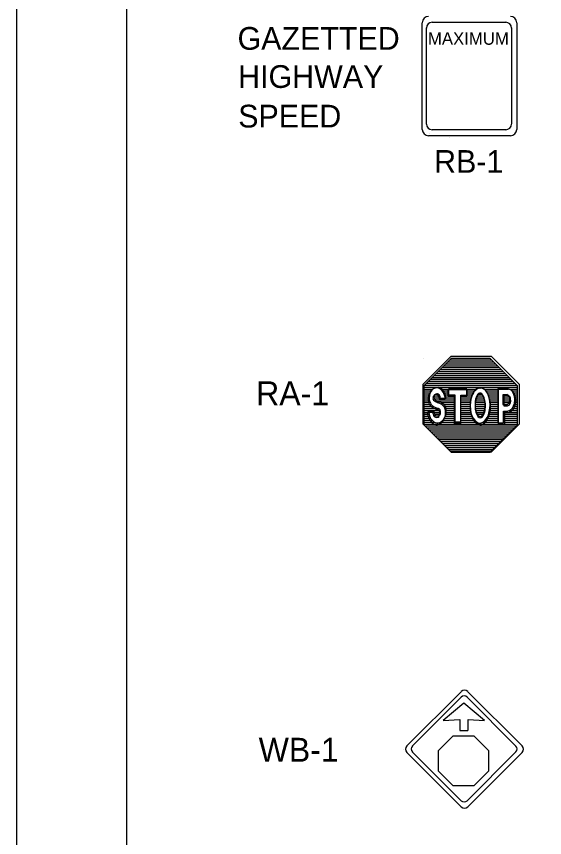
# Model space of a CAD drawing. Extents: x 1314 to 1530, y 165 to 444.
# Drawn here: x 1313.8 to 1361.9, y 296.1 to 370.9 of the extents above; entities that cross this region are included whole.
import ezdxf

# ---------------------------------------------------------------- set-up
doc = ezdxf.new("R2010")
doc.units = 0
for name, color, linetype in [('Level 10', 7, 'Continuous'), ('Level 44', 7, 'Continuous'), ('Level 60', 7, 'Continuous')]:
    doc.layers.add(name, color=color, linetype=linetype)

msp = doc.modelspace()

# ---------------------------------------------------------------- linework, layer by layer
at = {"layer": 'Level 10'}
msp.add_lwpolyline([(1353.534, 305.411), (1355.421, 305.411), (1356.754, 304.079), (1356.754, 302.198), (1355.421, 300.865), (1353.534, 300.865), (1352.208, 302.198), (1352.208, 304.079)], close=True, dxfattribs=at)
at = {"layer": 'Level 44'}
for p, q in [((1350.724, 360.601), (1350.724, 370.311)), ((1351.624, 370.349), (1358.328, 370.349)), ((1359.322, 370.311), (1359.322, 360.601)), ((1351.107, 361.094), (1351.107, 369.832)), ((1358.846, 369.832), (1358.846, 361.094)), ((1351.107, 361.091), (1351.107, 361.094)), ((1350.724, 360.598), (1350.724, 360.601)), ((1351.43, 360.265), (1351.43, 360.265)), ((1358.328, 360.575), (1351.624, 360.575)), ((1358.746, 360.025), (1351.298, 360.025)), ((1353.178, 359.867), (1353.178, 359.867)), ((1353.375, 339.742), (1350.888, 337.256)), ((1350.888, 339.742), (1350.888, 339.742)), ((1356.916, 339.742), (1353.375, 339.742)), ((1359.403, 337.256), (1356.916, 339.742)), ((1350.888, 337.256), (1350.888, 333.714)), ((1359.403, 333.714), (1359.403, 337.256)), ((1353.083, 336.359), (1353.083, 336.918)), ((1353.083, 336.918), (1354.782, 336.918)), ((1353.671, 336.359), (1353.083, 336.359)), ((1353.134, 336.986), (1353.134, 336.441)), ((1354.791, 336.986), (1353.134, 336.986)), ((1353.134, 336.441), (1353.708, 336.441)), ((1353.671, 333.848), (1353.671, 336.359)), ((1353.708, 336.441), (1353.708, 333.99)), ((1354.782, 336.345), (1354.223, 336.345)), ((1354.223, 336.345), (1354.223, 333.848)), ((1354.246, 333.99), (1354.246, 336.427)), ((1354.246, 336.427), (1354.791, 336.427)), ((1354.782, 336.918), (1354.782, 336.345)), ((1354.791, 336.427), (1354.791, 336.986)), ((1355.958, 336.516), (1355.981, 336.52)), ((1355.98, 337.059), (1355.996, 337.06)), ((1358.489, 337.015), (1357.618, 337.015)), ((1357.618, 337.015), (1357.618, 333.898)), ((1357.677, 333.754), (1357.677, 336.947)), ((1357.677, 336.947), (1358.571, 336.947)), ((1358.411, 336.456), (1358.07, 336.456)), ((1358.07, 336.456), (1358.07, 335.549)), ((1358.07, 336.456), (1358.07, 335.549)), ((1358.411, 336.456), (1358.07, 336.456)), ((1358.143, 336.374), (1358.143, 335.445)), ((1358.49, 336.374), (1358.143, 336.374)), ((1358.49, 336.374), (1358.143, 336.374)), ((1358.143, 336.374), (1358.143, 335.445)), ((1352.822, 336.025), (1352.277, 336.025)), ((1352.879, 336.116), (1352.347, 336.116)), ((1351.204, 334.879), (1351.704, 334.879)), ((1351.299, 334.996), (1351.788, 334.996)), ((1358.07, 335.549), (1358.404, 335.549)), ((1358.07, 335.549), (1358.404, 335.549)), ((1358.134, 333.898), (1358.134, 334.961)), ((1358.134, 334.961), (1358.461, 334.961)), ((1358.143, 335.445), (1358.483, 335.445)), ((1358.143, 335.445), (1358.483, 335.445)), ((1358.525, 334.85), (1358.207, 334.842)), ((1358.207, 334.842), (1358.541, 334.842)), ((1358.207, 334.842), (1358.207, 333.754)), ((1351.363, 334.247), (1351.36, 334.249)), ((1350.888, 333.714), (1353.375, 331.228)), ((1354.223, 333.848), (1353.671, 333.848)), ((1353.708, 333.99), (1354.246, 333.99)), ((1356.916, 331.228), (1359.403, 333.714)), ((1357.618, 333.898), (1358.134, 333.898)), ((1358.207, 333.754), (1357.677, 333.754)), ((1353.375, 331.228), (1356.916, 331.228)), ((1354.283, 309.427), (1349.335, 304.486)), ((1359.809, 304.486), (1354.868, 309.427)), ((1349.829, 304.482), (1354.283, 308.929)), ((1354.808, 308.929), (1359.256, 304.482)), ((1354.518, 308.391), (1352.648, 306.814)), ((1356.388, 306.814), (1354.518, 308.391)), ((1352.648, 306.814), (1354.143, 306.895)), ((1354.143, 306.895), (1354.143, 305.896)), ((1354.893, 305.896), (1354.893, 306.895)), ((1354.893, 306.895), (1356.388, 306.814)), ((1354.143, 305.896), (1354.888, 305.896)), ((1349.04, 304.196), (1349.04, 304.196)), ((1349.335, 303.899), (1354.283, 298.952)), ((1349.338, 303.899), (1349.335, 303.899)), ((1354.283, 299.503), (1349.829, 303.953)), ((1359.256, 303.953), (1354.808, 299.503)), ((1354.868, 298.952), (1359.809, 303.899))]:
    msp.add_line(p, q, dxfattribs=at)
msp.add_lwpolyline([(1359.552, 333.776), (1357.004, 331.228), (1353.375, 331.228), (1350.827, 333.776), (1350.827, 337.405), (1353.375, 339.953), (1357.004, 339.953), (1359.552, 337.405)], close=True, dxfattribs=at)
for points in [[(1353.084, 339.452), (1357.2, 339.452)], [(1353.261, 339.628), (1357.029, 339.628)], [(1352.199, 338.566), (1358.092, 338.566)], [(1352.376, 338.743), (1357.915, 338.743)], [(1352.553, 338.92), (1357.73, 338.92)], [(1352.73, 339.097), (1357.561, 339.097)], [(1352.907, 339.274), (1357.383, 339.274)], [(1351.49, 337.858), (1358.8, 337.858)], [(1351.667, 338.035), (1358.623, 338.035)], [(1351.844, 338.212), (1358.446, 338.212)], [(1352.022, 338.389), (1358.269, 338.389)], [(1350.888, 337.149), (1359.403, 337.149)], [(1350.959, 337.327), (1359.332, 337.327)], [(1351.136, 337.503), (1359.154, 337.503)], [(1351.314, 337.681), (1358.978, 337.681)], [(1350.888, 336.972), (1351.71, 336.972)], [(1350.888, 336.795), (1351.561, 336.795)], [(1350.888, 336.618), (1351.462, 336.618)], [(1350.888, 336.441), (1351.412, 336.441)], [(1351.88, 336.441), (1352.276, 336.441)], [(1352.525, 336.972), (1353.134, 336.972)], [(1352.68, 336.795), (1353.134, 336.795)], [(1352.779, 336.618), (1353.134, 336.618)], [(1352.829, 336.441), (1353.134, 336.441)], [(1354.791, 336.972), (1355.612, 336.972)], [(1354.791, 336.795), (1355.45, 336.795)], [(1354.791, 336.618), (1355.329, 336.618)], [(1354.791, 336.441), (1355.252, 336.441)], [(1355.733, 336.441), (1356.229, 336.441)], [(1356.364, 336.972), (1357.618, 336.972)], [(1356.533, 336.795), (1357.618, 336.795)], [(1356.647, 336.618), (1357.618, 336.618)], [(1356.725, 336.441), (1357.618, 336.441)], [(1358.07, 336.441), (1358.481, 336.441)], [(1358.651, 336.972), (1359.403, 336.972)], [(1358.878, 336.795), (1359.403, 336.795)], [(1358.991, 336.618), (1359.403, 336.618)], [(1359.076, 336.441), (1359.403, 336.441)], [(1350.888, 336.264), (1351.378, 336.264)], [(1350.888, 336.087), (1351.37, 336.087)], [(1350.888, 335.91), (1351.391, 335.91)], [(1350.888, 335.733), (1351.441, 335.733)], [(1351.802, 336.264), (1352.354, 336.264)], [(1351.83, 336.087), (1353.708, 336.087)], [(1352.057, 335.91), (1353.708, 335.91)], [(1352.454, 335.733), (1353.708, 335.733)], [(1352.872, 336.264), (1353.708, 336.264)], [(1354.246, 336.264), (1355.188, 336.264)], [(1354.246, 336.087), (1355.145, 336.087)], [(1354.246, 335.91), (1355.117, 335.91)], [(1354.253, 335.733), (1355.096, 335.733)], [(1355.542, 335.733), (1356.441, 335.733)], [(1355.549, 335.91), (1356.413, 335.91)], [(1355.599, 336.087), (1356.371, 336.087)], [(1355.648, 336.264), (1356.314, 336.264)], [(1356.788, 336.264), (1357.618, 336.264)], [(1356.831, 336.087), (1357.618, 336.087)], [(1356.866, 335.91), (1357.618, 335.91)], [(1356.881, 335.733), (1357.618, 335.733)], [(1358.064, 335.91), (1358.701, 335.91)], [(1358.07, 336.264), (1358.651, 336.264)], [(1358.07, 336.087), (1358.694, 336.087)], [(1358.07, 335.733), (1358.644, 335.733)], [(1359.119, 336.264), (1359.403, 336.264)], [(1359.126, 335.733), (1359.403, 335.733)], [(1359.14, 336.087), (1359.403, 336.087)], [(1359.147, 335.91), (1359.403, 335.91)], [(1350.888, 335.555), (1351.554, 335.555)], [(1350.888, 335.378), (1351.781, 335.378)], [(1350.888, 335.202), (1352.199, 335.202)], [(1350.888, 335.025), (1352.383, 335.025)], [(1350.888, 334.847), (1351.32, 334.847)], [(1351.802, 334.847), (1352.404, 334.847)], [(1352.694, 335.555), (1353.708, 335.555)], [(1352.829, 335.378), (1353.708, 335.378)], [(1352.879, 335.202), (1353.708, 335.202)], [(1352.907, 335.025), (1353.708, 335.025)], [(1352.907, 334.847), (1353.708, 334.847)], [(1354.246, 335.555), (1355.089, 335.555)], [(1354.246, 335.378), (1355.089, 335.378)], [(1354.246, 335.202), (1355.103, 335.202)], [(1354.246, 335.025), (1355.125, 335.025)], [(1354.246, 334.847), (1355.153, 334.847)], [(1355.528, 335.555), (1356.441, 335.555)], [(1355.528, 335.378), (1356.448, 335.378)], [(1355.549, 335.202), (1356.427, 335.202)], [(1355.584, 335.025), (1356.392, 335.025)], [(1355.641, 334.847), (1356.343, 334.847)], [(1356.81, 334.847), (1357.618, 334.847)], [(1356.845, 335.025), (1357.618, 335.025)], [(1356.874, 335.202), (1357.618, 335.202)], [(1356.888, 335.378), (1357.618, 335.378)], [(1356.895, 335.555), (1357.618, 335.555)], [(1358.134, 334.847), (1359.403, 334.847)], [(1358.651, 335.025), (1359.403, 335.025)], [(1358.893, 335.202), (1359.403, 335.202)], [(1359.012, 335.378), (1359.403, 335.378)], [(1359.076, 335.555), (1359.403, 335.555)], [(1350.888, 334.67), (1351.355, 334.67)], [(1350.888, 334.493), (1351.412, 334.493)], [(1350.888, 334.316), (1351.497, 334.316)], [(1350.888, 334.139), (1351.639, 334.139)], [(1351.858, 334.67), (1352.362, 334.67)], [(1352.624, 334.139), (1353.708, 334.139)], [(1352.751, 334.316), (1353.708, 334.316)], [(1352.836, 334.493), (1353.708, 334.493)], [(1352.893, 334.67), (1353.708, 334.67)], [(1354.246, 334.67), (1355.202, 334.67)], [(1354.246, 334.493), (1355.266, 334.493)], [(1354.246, 334.316), (1355.358, 334.316)], [(1354.246, 334.139), (1355.486, 334.139)], [(1355.719, 334.67), (1356.25, 334.67)], [(1356.471, 334.139), (1357.618, 334.139)], [(1356.597, 334.316), (1357.618, 334.316)], [(1356.69, 334.493), (1357.618, 334.493)], [(1356.76, 334.67), (1357.618, 334.67)], [(1358.134, 334.67), (1359.403, 334.67)], [(1358.134, 334.493), (1359.403, 334.493)], [(1358.134, 334.316), (1359.403, 334.316)], [(1358.134, 334.139), (1359.403, 334.139)], [(1350.888, 333.962), (1351.844, 333.962)], [(1350.888, 333.785), (1359.403, 333.785)], [(1350.994, 333.608), (1359.295, 333.608)], [(1351.172, 333.43), (1359.119, 333.43)], [(1352.39, 333.962), (1355.698, 333.962)], [(1356.258, 333.962), (1357.618, 333.962)], [(1358.134, 333.962), (1359.403, 333.962)], [(1351.349, 333.253), (1358.942, 333.253)], [(1351.526, 333.077), (1358.765, 333.077)], [(1351.703, 332.899), (1358.587, 332.899)], [(1351.88, 332.722), (1358.411, 332.722)], [(1352.057, 332.545), (1358.233, 332.545)], [(1352.234, 332.369), (1358.057, 332.369)], [(1352.411, 332.191), (1357.879, 332.191)], [(1352.589, 332.014), (1357.702, 332.014)], [(1352.765, 331.837), (1357.525, 331.837)], [(1352.943, 331.66), (1357.349, 331.66)], [(1353.126, 331.483), (1357.171, 331.483)], [(1353.297, 331.306), (1356.994, 331.306)]]:
    msp.add_lwpolyline(points, dxfattribs=at)
for centre, radius, start, end in [((1351.299, 370.31), 0.575, 90, 179.99999), ((1358.747, 370.31), 0.575, 359.99999, 89.99999), ((1351.625, 369.83), 0.517, 90, 179.99999), ((1358.328, 369.83), 0.517, 359.99999, 89.99999), ((1351.625, 361.091), 0.517, 180, 269.99999), ((1358.328, 361.091), 0.517, 270, 359.99999), ((1351.299, 360.599), 0.575, 180, 269.99999), ((1358.747, 360.599), 0.575, 270, 359.99999), ((1352.039, 336.483), 0.591, 46.13686, 121.39871), ((1352.114, 336.562), 0.577, 46.13686, 121.39871), ((1352.632, 336.062), 1.355, 157.73321, 177.13918), ((1352.693, 336.151), 1.322, 157.73321, 177.13918), ((1352.261, 336.179), 0.967, 123.3662, 155.67344), ((1352.331, 336.265), 0.944, 123.3662, 155.67344), ((1352.011, 336.17), 0.294, 113.8064, 172.24074), ((1352.087, 336.257), 0.287, 113.8064, 172.24074), ((1351.988, 336.147), 0.308, 47.30173, 109.01194), ((1352.064, 336.234), 0.3, 47.30173, 109.01194), ((1351.844, 336.093), 0.449, 350.44122, 39.32441), ((1351.924, 336.181), 0.439, 350.44121, 39.32441), ((1351.792, 336.159), 0.998, 14.56402, 49.00631), ((1351.873, 336.245), 0.974, 14.56402, 49.00631), ((1351.438, 336.001), 1.381, 0.69518, 17.14515), ((1351.528, 336.092), 1.348, 0.69517, 17.14515), ((1358.358, 336.161), 0.307, 35.11978, 79.31166), ((1358.358, 336.161), 0.307, 35.11978, 79.31166), ((1358.442, 336.502), 0.517, 44.85284, 85.0441), ((1358.437, 336.072), 0.315, 35.11978, 79.31166), ((1358.437, 336.072), 0.315, 35.11978, 79.31166), ((1358.523, 336.422), 0.53, 44.85284, 85.0441), ((1358.215, 336.069), 0.477, 8.60306, 34.21696), ((1358.215, 336.069), 0.477, 8.60306, 34.21696), ((1358.28, 336.275), 0.794, 29.22414, 48.53082), ((1358.28, 336.275), 0.794, 29.22414, 48.53082), ((1358.357, 336.189), 0.814, 29.22414, 48.53082), ((1358.357, 336.189), 0.814, 29.22414, 48.53082), ((1358.27, 336.198), 0.843, 13.06738, 33.76202), ((1358.346, 336.11), 0.864, 13.06738, 33.76202), ((1357.512, 335.949), 1.639, 3.39027, 15.65974), ((1352.465, 336.025), 1.19, 174.81715, 195.91834), ((1352.115, 335.99), 0.847, 200.4481, 235.11069), ((1352.53, 336.115), 1.161, 174.81715, 195.91834), ((1352.189, 336.08), 0.826, 200.44809, 235.11069), ((1351.976, 336.128), 0.268, 164.13099, 238.14757), ((1352.053, 336.216), 0.262, 164.13098, 238.14757), ((1352.824, 337.482), 1.866, 237.98164, 250.97904), ((1352.881, 337.537), 1.821, 237.98164, 250.97904), ((1351.728, 334.507), 1.305, 46.24648, 67.92633), ((1351.811, 334.634), 1.274, 46.24648, 67.92633), ((1358.332, 335.894), 0.352, 281.91913, 325.78679), ((1358.332, 335.894), 0.352, 281.91913, 325.78679), ((1358.41, 335.799), 0.361, 281.91914, 325.7868), ((1358.41, 335.799), 0.361, 281.91914, 325.7868), ((1358.245, 335.946), 0.453, 326.50855, 357.0313), ((1358.245, 335.946), 0.453, 326.50855, 357.0313), ((1358.197, 336.007), 0.507, 350.34164, 15.2342), ((1358.197, 336.007), 0.507, 350.34164, 15.2342), ((1358.29, 335.978), 0.489, 8.60306, 34.21696), ((1358.29, 335.978), 0.489, 8.60306, 34.21696), ((1358.321, 335.852), 0.464, 326.50855, 357.0313), ((1358.321, 335.852), 0.464, 326.50855, 357.0313), ((1358.272, 335.915), 0.52, 350.34165, 15.23421), ((1358.272, 335.915), 0.52, 350.34165, 15.23421), ((1357.441, 336.084), 1.721, 338.31533, 348.66985), ((1357.833, 335.981), 1.317, 349.75207, 2.79164), ((1357.833, 335.981), 1.317, 349.75207, 2.79164), ((1357.497, 335.993), 1.764, 338.31533, 348.66985), ((1357.57, 335.855), 1.68, 3.39027, 15.65974), ((1357.898, 335.888), 1.35, 349.75207, 2.79164), ((1357.898, 335.888), 1.35, 349.75207, 2.79164), ((1352.873, 334.953), 1.669, 182.38409, 204.95188), ((1352.929, 335.069), 1.629, 182.38408, 204.95187), ((1354.284, 340.825), 6.134, 244.46241, 248.83121), ((1352.46, 334.871), 0.761, 179.01715, 193.51721), ((1354.305, 340.8), 5.987, 244.46241, 248.83121), ((1352.525, 334.988), 0.743, 179.01714, 193.51721), ((1351.969, 334.731), 0.387, 34.20826, 74.15525), ((1352.046, 334.852), 0.377, 34.20826, 74.15525), ((1351.98, 334.772), 0.355, 352.57609, 30.47756), ((1351.953, 334.851), 0.447, 326.25303, 358.73226), ((1352.057, 334.892), 0.346, 352.57608, 30.47755), ((1354.397, 336.895), 2.281, 219.47897, 223.42605), ((1354.415, 336.964), 2.226, 219.47896, 223.42604), ((1351.493, 334.799), 1.359, 5.90969, 21.9865), ((1351.581, 334.919), 1.326, 5.90969, 21.98649), ((1350.925, 334.803), 1.924, 351.24702, 3.9864), ((1351.027, 334.923), 1.878, 351.24702, 3.9864), ((1358.476, 335.146), 0.18, 259.79086, 293.54186), ((1358.558, 335.032), 0.184, 259.79086, 293.54187), ((1358.323, 335.712), 0.765, 286.60197, 299.80905), ((1358.4, 335.612), 0.784, 286.60198, 299.80906), ((1358.477, 335.514), 0.518, 295.38384, 322.61875), ((1358.558, 335.409), 0.531, 295.38384, 322.61875), ((1358.259, 335.754), 0.84, 318.29224, 338.60313), ((1358.259, 335.754), 0.84, 318.29225, 338.60313), ((1358.335, 335.655), 0.86, 318.29225, 338.60313), ((1358.335, 335.655), 0.86, 318.29225, 338.60313), ((1352.409, 334.813), 1.189, 208.41538, 233.65531), ((1352.476, 334.932), 1.16, 208.41537, 233.6553), ((1352.102, 334.727), 0.382, 186.87276, 222.74491), ((1352.176, 334.848), 0.373, 186.87276, 222.74491), ((1352.051, 334.762), 0.372, 230.6966, 271.45727), ((1352.126, 334.882), 0.363, 230.6966, 271.45727), ((1352.023, 334.733), 0.345, 275.4374, 314.06255), ((1352.099, 334.854), 0.337, 275.4374, 314.06255), ((1351.911, 334.578), 0.868, 293.14132, 324.99056), ((1351.873, 334.73), 0.459, 326.25303, 358.73226), ((1351.99, 334.703), 0.847, 293.14132, 324.99055), ((1351.376, 334.937), 1.512, 325.50918, 343.2894), ((1351.467, 335.053), 1.476, 325.50918, 343.2894), ((1352.039, 334.284), 0.544, 232.05359, 292.73967), ((1352.114, 334.416), 0.531, 232.05359, 292.73967), ((1354.574, 309.135), 0.414, 45, 135), ((1354.545, 308.666), 0.372, 45, 135), ((1349.63, 304.192), 0.414, 135, 224.99999), ((1350.095, 304.217), 0.372, 135, 224.99999), ((1358.994, 304.217), 0.372, 315, 45), ((1359.518, 304.192), 0.414, 315, 45), ((1354.545, 299.768), 0.372, 225, 315), ((1354.574, 299.248), 0.414, 225, 315)]:
    msp.add_arc(centre, radius, start, end, dxfattribs=at)
for centre, major_axis, ratio, start_param, end_param in [((1355.989, 335.502), (-0.011, -1.623), 0.558644, 3.185857, 9.451311), ((1356.009, 335.397), (-0.011, -1.663), 0.558644, 0.656861, 3.168126), ((1356.009, 335.397), (-0.011, -1.663), 0.558644, 4.129576, 6.939747), ((1356.009, 335.397), (-0.011, -1.663), 0.558644, 3.185857, 4.129398), ((1355.989, 335.54), (0.005, -1.06), 0.432619, 3.239639, 9.473919), ((1356.009, 335.435), (0.006, -1.086), 0.432619, 3.239639, 3.888884), ((1356.009, 335.435), (0.006, -1.086), 0.432619, 0.881967, 3.190734), ((1356.009, 335.435), (0.006, -1.086), 0.432619, 3.890436, 7.165085)]:
    msp.add_ellipse(centre, major_axis=major_axis, ratio=ratio, start_param=start_param, end_param=end_param, dxfattribs=at)
at = {"layer": 'Level 60'}
for points in [[(1529.816, 443.871), (1313.816, 443.871), (1313.816, 164.871), (1529.816, 164.871)], [(1510.69, 433.062), (1323.816, 433.062), (1323.816, 175.68), (1510.69, 175.68)]]:
    msp.add_lwpolyline(points, close=True, dxfattribs=at)

# ---------------------------------------------------------------- texts
at = {"layer": 'Level 10'}
for s, height, p in [('GAZETTED', 2.0682, (1333.93, 367.851)), ('HIGHWAY', 2.0682, (1333.981, 364.38)), ('SPEED', 2.0682, (1333.991, 360.775)), ('RB-1', 2.0682, (1351.812, 356.65)), ('RA-1', 2.1771, (1335.623, 335.492)), ('WB-1', 2.1771, (1335.851, 303.05))]:
    msp.add_text(s, height=height, rotation=360, dxfattribs=at).set_placement(p)
at = {"layer": 'Level 44'}
msp.add_text('MAXIMUM', height=1.1394, rotation=360, dxfattribs=at).set_placement((1351.248, 368.303))

doc.saveas('drawing.dxf')
